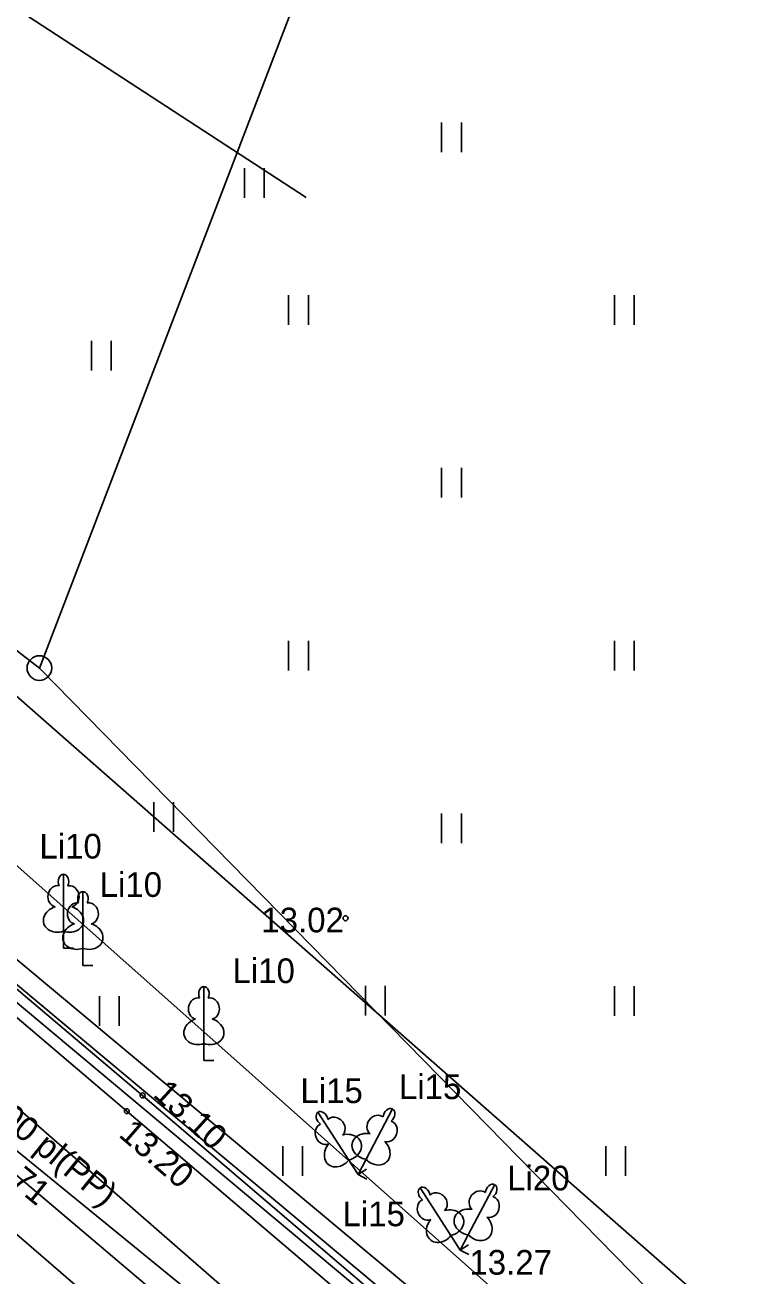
# Model space of a CAD drawing. Extents: x 503877 to 504025, y 304562 to 304725.
# Drawn here: x 503960.53 to 503975.24, y 304593.32 to 304618.66 of the extents above; entities that cross this region are included whole.
import ezdxf

# ---------------------------------------------------------------- set-up
doc = ezdxf.new("R2010")
doc.units = 0
for name, color, linetype in [('10', 7, 'Continuous'), ('20', 7, 'Continuous'), ('24', 7, 'Continuous'), ('25', 7, 'Continuous'), ('CELI_CMAL_####_####_#', 7, 'Continuous'), ('CELI_TAKA_####_####_#', 7, 'Continuous'), ('ELEK_VADV_ZSPR_####_#', 7, 'Continuous'), ('Level 46', 7, 'Continuous'), ('RELJ_AATZ_####_TKST_#', 7, 'Continuous'), ('RELJ_ELEM_####_####_#', 7, 'Continuous'), ('RELJ_HORZ_PAMT_####_#', 7, 'Continuous'), ('SAKK_KKAN_####_####_#', 7, 'Continuous'), ('SAKT_VADP_KABE_####_#', 7, 'Continuous'), ('SAKT_VADP_NEDR_####_#', 7, 'Continuous'), ('SKAN_VADP_PAST_####_I', 7, 'Continuous'), ('SKAN_VADP_PAST_TKST_I', 7, 'Continuous'), ('TERT_DIAM_####_TKST_#', 7, 'Continuous'), ('TERT_ELEM_####_####_#', 7, 'Continuous'), ('UDTK_VADP_NEDR_####_#', 7, 'Continuous'), ('UDTK_VADP_UDEN_####_I', 7, 'Continuous')]:
    doc.layers.add(name, color=color, linetype=linetype)

msp = doc.modelspace()

# ---------------------------------------------------------------- linework, layer by layer
at = {"layer": '10'}
msp.add_circle((503960.823, 304605.633), 0.25, dxfattribs=at)
at = {"layer": '20'}
msp.add_line((503960.823, 304605.633), (503983.332, 304582.665), dxfattribs=at)
at = {"layer": '24'}
for p, q in [((503978.978, 304653.014), (503960.823, 304605.633)), ((503960.823, 304605.633), (503933.144, 304627.024))]:
    msp.add_line(p, q, dxfattribs=at)
at = {"layer": '25'}
msp.add_line((503924.947, 304625.297), (503985.325, 304574.255), dxfattribs=at)
at = {"layer": 'CELI_CMAL_####_####_#'}
for p, q in [((503962.594, 304596.657), (503947.498, 304609.501)), ((503982.055, 304580.09), (503962.594, 304596.657))]:
    msp.add_line(p, q, dxfattribs=at)
at = {"layer": 'CELI_TAKA_####_####_#'}
for p, q in [((503947.74, 304609.79), (503962.913, 304596.977)), ((503962.913, 304596.977), (503982.372, 304580.35))]:
    msp.add_line(p, q, dxfattribs=at)
at = {"layer": 'ELEK_VADV_ZSPR_####_#'}
msp.add_line((503938.2, 304621.309), (503972.501, 304590.85), dxfattribs=at)
at = {"layer": 'Level 46'}
msp.add_line((503943.333, 304620.019), (504006.701, 304564.361), dxfattribs=at)
at = {"layer": 'RELJ_ELEM_####_####_#'}
for centre in [(503967.025, 304600.566), (503962.913, 304596.977), (503962.594, 304596.657)]:
    msp.add_circle(centre, 0.05, dxfattribs=at)
at = {"layer": 'RELJ_HORZ_PAMT_####_#'}
msp.add_line((503966.227, 304615.164), (503949.188, 304626.264), dxfattribs=at)
at = {"layer": 'SAKK_KKAN_####_####_#'}
msp.add_line((503968.613, 304591.954), (503945.607, 304611.208), dxfattribs=at)
at = {"layer": 'SAKT_VADP_KABE_####_#'}
msp.add_line((503971.653, 304590.306), (503940.354, 304616.433), dxfattribs=at)
at = {"layer": 'SAKT_VADP_NEDR_####_#'}
msp.add_line((503997.217, 304568.475), (503924.507, 304629.123), dxfattribs=at)
at = {"layer": 'SKAN_VADP_PAST_####_I'}
msp.add_line((503973.287, 304585.319), (503945.224, 304608.195), dxfattribs=at)
at = {"layer": 'TERT_ELEM_####_####_#'}
for p, q in [((503968.971, 304616.087), (503968.971, 304616.687)), ((503969.371, 304616.087), (503969.371, 304616.687)), ((503964.979, 304615.162), (503964.979, 304615.762)), ((503965.379, 304615.162), (503965.379, 304615.762)), ((503965.871, 304612.587), (503965.871, 304613.187)), ((503966.271, 304612.587), (503966.271, 304613.187)), ((503972.471, 304612.587), (503972.471, 304613.187)), ((503972.871, 304612.587), (503972.871, 304613.187)), ((503961.879, 304611.662), (503961.879, 304612.262)), ((503962.279, 304611.662), (503962.279, 304612.262)), ((503968.971, 304609.087), (503968.971, 304609.687)), ((503969.371, 304609.087), (503969.371, 304609.687)), ((503965.871, 304605.587), (503965.871, 304606.187)), ((503966.271, 304605.587), (503966.271, 304606.187)), ((503972.471, 304605.587), (503972.471, 304606.187)), ((503972.871, 304605.587), (503972.871, 304606.187)), ((503963.138, 304602.315), (503963.138, 304602.915)), ((503963.538, 304602.315), (503963.538, 304602.915)), ((503968.971, 304602.087), (503968.971, 304602.687)), ((503969.371, 304602.087), (503969.371, 304602.687)), ((503961.311, 304600.304), (503961.311, 304599.957)), ((503961.311, 304599.957), (503961.511, 304599.957)), ((503961.704, 304599.956), (503961.704, 304599.609)), ((503961.704, 304599.609), (503961.904, 304599.609)), ((503967.429, 304598.597), (503967.429, 304599.197)), ((503967.829, 304598.597), (503967.829, 304599.197)), ((503972.471, 304598.587), (503972.471, 304599.187)), ((503972.871, 304598.587), (503972.871, 304599.187)), ((503962.039, 304598.387), (503962.039, 304598.987)), ((503962.439, 304598.387), (503962.439, 304598.987)), ((503964.155, 304598.029), (503964.155, 304597.682)), ((503964.155, 304597.682), (503964.355, 304597.682)), ((503965.754, 304595.35), (503965.754, 304595.95)), ((503966.154, 304595.35), (503966.154, 304595.95)), ((503972.295, 304595.35), (503972.295, 304595.95)), ((503972.695, 304595.35), (503972.695, 304595.95)), ((503967.09, 304595.668), (503967.278, 304595.376)), ((503967.439, 304595.683), (503967.278, 304595.376)), ((503967.278, 304595.376), (503967.446, 304595.484)), ((503967.278, 304595.376), (503967.455, 304595.283)), ((503969.159, 304594.137), (503969.347, 304593.845)), ((503969.508, 304594.152), (503969.347, 304593.845)), ((503969.347, 304593.845), (503969.515, 304593.953)), ((503969.347, 304593.845), (503969.524, 304593.752))]:
    msp.add_line(p, q, dxfattribs=at)
for points in [[(503961.311, 304601.457), (503961.311, 304600.304)], [(503961.401, 304601.225), (503961.4, 304601.226)], [(503961.704, 304601.109), (503961.704, 304599.956)], [(503961.794, 304600.877), (503961.793, 304600.878)], [(503964.155, 304599.182), (503964.155, 304598.029)], [(503964.245, 304598.95), (503964.244, 304598.951)], [(503966.466, 304596.637), (503967.09, 304595.668)], [(503966.667, 304596.49), (503966.666, 304596.491)], [(503967.976, 304596.704), (503967.439, 304595.683)], [(503967.947, 304596.456), (503967.946, 304596.458)], [(503968.535, 304595.106), (503969.159, 304594.137)], [(503968.736, 304594.959), (503968.735, 304594.96)], [(503970.045, 304595.173), (503969.508, 304594.152)], [(503970.016, 304594.925), (503970.015, 304594.927)]]:
    msp.add_lwpolyline(points, dxfattribs=at)
for centre, major_axis, ratio, start_param, end_param in [((503961.311, 304601.307), (0, -0.15), 0.707107, 3.14537, 5.287485), ((503961.311, 304601.307), (0, -0.15), 0.707107, 0.995701, 3.137816), ((503961.183, 304601.012), (-0.039, -0.212), 0.861323, 3.141593, 6.283185), ((503961.439, 304601.012), (0.039, -0.212), 0.861323, 0, 3.141593), ((503961.704, 304600.959), (0, -0.15), 0.707107, 3.14537, 5.287485), ((503961.704, 304600.959), (0, -0.15), 0.707107, 0.995701, 3.137816), ((503961.221, 304600.55), (0.307, 0.095), 0.814445, 1.570796, 4.752015), ((503961.401, 304600.55), (-0.307, 0.095), 0.814445, 1.531171, 4.712389), ((503961.576, 304600.664), (-0.039, -0.212), 0.861323, 3.141593, 6.283185), ((503961.832, 304600.664), (0.039, -0.212), 0.861323, 0, 3.141593), ((503961.614, 304600.202), (0.307, 0.095), 0.814445, 1.570796, 4.752015), ((503961.794, 304600.202), (-0.307, 0.095), 0.814445, 1.531171, 4.712389), ((503964.155, 304599.032), (0, -0.15), 0.707107, 3.14537, 5.287485), ((503964.155, 304599.032), (0, -0.15), 0.707107, 0.995701, 3.137816), ((503964.027, 304598.737), (-0.039, -0.212), 0.861323, 3.141593, 6.283185), ((503964.283, 304598.737), (0.039, -0.212), 0.861323, 0, 3.141593), ((503964.065, 304598.275), (0.307, 0.095), 0.814445, 1.570796, 4.752015), ((503964.245, 304598.275), (-0.307, 0.095), 0.814445, 1.531171, 4.712389), ((503966.548, 304596.511), (0.081, -0.126), 0.707107, 3.14537, 5.287485), ((503966.547, 304596.511), (0.081, -0.126), 0.707107, 0.995701, 3.137816), ((503966.815, 304596.333), (0.148, -0.158), 0.861323, 0, 3.141593), ((503967.655, 304596.37), (-0.133, -0.17), 0.861323, 3.141593, 6.283185), ((503967.906, 304596.571), (-0.07, -0.133), 0.707107, 3.14537, 5.287485), ((503967.906, 304596.571), (-0.07, -0.133), 0.707107, 0.995701, 3.137816), ((503966.599, 304596.194), (0.082, -0.2), 0.861323, 3.141593, 6.283185), ((503967.882, 304596.25), (-0.065, -0.206), 0.861323, 0, 3.141593), ((503966.882, 304595.826), (0.206, 0.246), 0.814445, 1.570796, 4.752015), ((503967.032, 304595.923), (-0.309, -0.086), 0.814445, 1.531171, 4.712389), ((503967.474, 304595.943), (0.316, -0.059), 0.814445, 1.570796, 4.752015), ((503967.633, 304595.859), (-0.227, 0.227), 0.814445, 1.531171, 4.712389), ((503968.617, 304594.98), (0.081, -0.126), 0.707107, 3.14537, 5.287485), ((503968.616, 304594.98), (0.081, -0.126), 0.707107, 0.995701, 3.137816), ((503968.884, 304594.802), (0.148, -0.158), 0.861323, 0, 3.141593), ((503969.724, 304594.839), (-0.133, -0.17), 0.861323, 3.141593, 6.283185), ((503969.975, 304595.04), (-0.07, -0.133), 0.707107, 3.14537, 5.287485), ((503969.975, 304595.04), (-0.07, -0.133), 0.707107, 0.995701, 3.137816), ((503968.668, 304594.663), (0.082, -0.2), 0.861323, 3.141593, 6.283185), ((503969.951, 304594.719), (-0.065, -0.206), 0.861323, 0, 3.141593), ((503968.951, 304594.295), (0.206, 0.246), 0.814445, 1.570796, 4.752015), ((503969.101, 304594.392), (-0.309, -0.086), 0.814445, 1.531171, 4.712389), ((503969.543, 304594.412), (0.316, -0.059), 0.814445, 1.570796, 4.752015), ((503969.702, 304594.328), (-0.227, 0.227), 0.814445, 1.531171, 4.712389)]:
    msp.add_ellipse(centre, major_axis=major_axis, ratio=ratio, start_param=start_param, end_param=end_param, dxfattribs=at)
at = {"layer": 'UDTK_VADP_NEDR_####_#'}
msp.add_line((503972.119, 304584.039), (503959.145, 304595.208), dxfattribs=at)
at = {"layer": 'UDTK_VADP_UDEN_####_I'}
msp.add_line((503942.658, 304612.162), (503968.511, 304589.634), dxfattribs=at)

# ---------------------------------------------------------------- texts
at = {"layer": 'RELJ_AATZ_####_TKST_#'}
for s, p in [(' 13.02', (503965.132, 304600.279)), (' 13.27', (503969.347, 304593.345))]:
    msp.add_text(s, height=0.5, dxfattribs=at).set_placement(p)
for s, rotation, p in [(' 13.10', 317.5496, (503962.966, 304597.096)), (' 13.20', 319.1132, (503962.267, 304596.279))]:
    msp.add_text(s, height=0.5, rotation=rotation, dxfattribs=at).set_placement(p)
at = {"layer": 'SKAN_VADP_PAST_TKST_I'}
for s, p in [('d200 pl(PP)', (503959.399, 304596.929)), ('c.a.9.71', (503958.934, 304596.224))]:
    msp.add_text(s, height=0.5, rotation=320.8143, dxfattribs=at).set_placement(p)
at = {"layer": 'TERT_DIAM_####_TKST_#'}
for s, p in [('Li10', (503960.823, 304601.775)), ('Li10', (503962.044, 304600.998)), ('Li10', (503964.734, 304599.252)), ('Li15', (503966.11, 304596.821)), ('Li15', (503968.106, 304596.902)), ('Li20', (503970.298, 304595.052)), ('Li15', (503966.963, 304594.327))]:
    msp.add_text(s, height=0.5, dxfattribs=at).set_placement(p)

doc.saveas('drawing.dxf')
